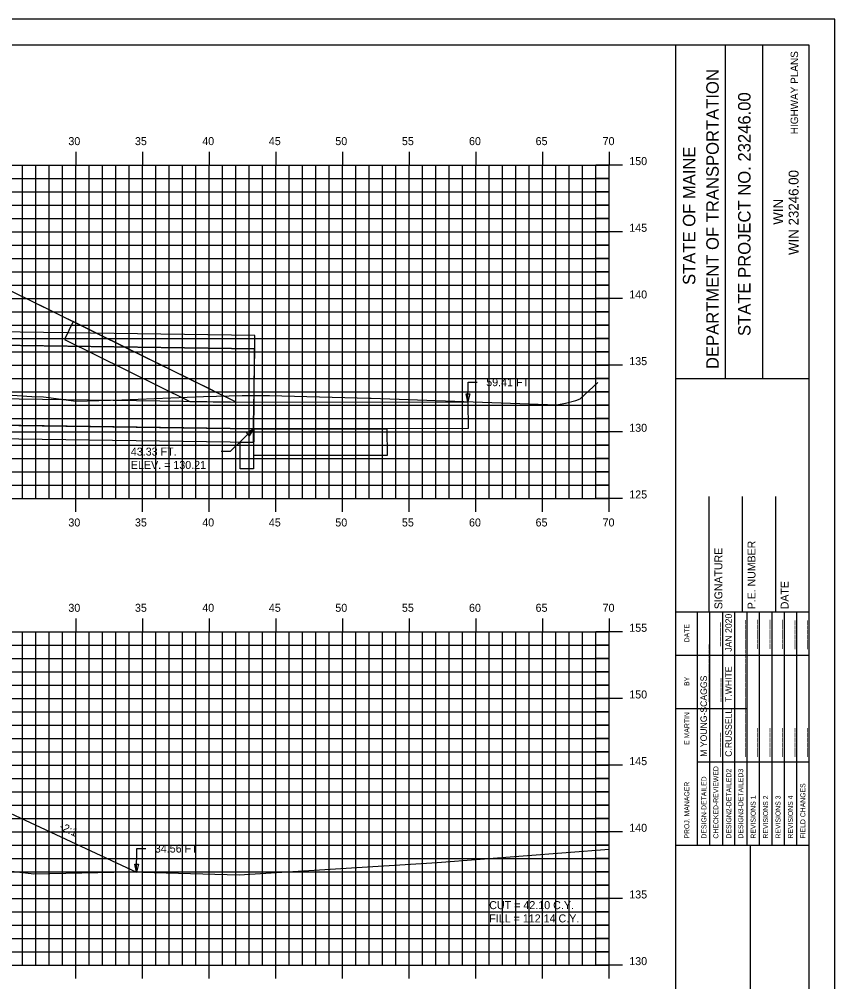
# Model space of a CAD drawing. Extents: x 1143863 to 1144033, y 608981 to 609091.
# Drawn here: x 1143972.4 to 1144033.5, y 609019.1 to 609091.3 of the extents above; entities that cross this region are included whole.
import ezdxf

# ---------------------------------------------------------------- set-up
doc = ezdxf.new("R2010")
doc.units = 0
for name, color, linetype in [('ANNOTATION', 7, 'Continuous'), ('BORDER', 7, 'Continuous'), ('D_Drainage_Culvert', 7, 'Continuous'), ('D_Roadway_SlopeLines', 7, 'Continuous'), ('D_Text_Standard', 7, 'Continuous'), ('H_V ANNOTATION', 7, 'Continuous'), ('HIGHWAY_TITLE', 7, 'Continuous'), ('MAJOR', 7, 'Continuous'), ('MINOR', 7, 'Continuous'), ('PATTERNING', 7, 'Continuous'), ('PLOT BOUNDARY', 7, 'Continuous'), ('S_Roadway_Centerline', 7, 'Continuous')]:
    doc.layers.add(name, color=color, linetype=linetype)

msp = doc.modelspace()

# ---------------------------------------------------------------- linework, layer by layer
for points in [[(1143971.726, 609070.91), (1143973.407, 609070.08), (1143974.229, 609069.674), (1143978.455, 609067.588), (1143981.694, 609065.99), (1143983.555, 609065.071), (1143987.715, 609063.019)], [(1143915.832, 609031.661), (1143916.276, 609031.761), (1143916.721, 609031.769), (1143917.165, 609031.685), (1143917.609, 609031.509), (1143921.469, 609032.509), (1143931.592, 609035.131), (1143931.593, 609035.131), (1143935.593, 609035.291), (1143946.593, 609035.511), (1143957.593, 609035.291), (1143964.593, 609035.011), (1143969.901, 609032.545), (1143972.053, 609031.545), (1143981.155, 609027.316)]]:
    msp.add_lwpolyline(points)
at = {"layer": 'BORDER'}
for p, q in [((1144021.593, 608984.335), (1144021.593, 609089.335)), ((1144025.321, 609064.332), (1144025.321, 609089.332)), ((1144028.117, 609064.332), (1144028.117, 609089.332)), ((1144021.594, 609064.329), (1144031.593, 609064.329)), ((1144024.093, 609046.838), (1144024.093, 609055.485)), ((1144026.593, 609046.838), (1144026.593, 609055.485)), ((1144029.093, 609046.838), (1144029.093, 609055.485)), ((1144021.593, 609046.838), (1144031.593, 609046.838)), ((1144021.593, 609029.338), (1144031.593, 609029.338)), ((1144027.184, 608994.338), (1144027.184, 609029.338))]:
    msp.add_line(p, q, dxfattribs=at)
msp.add_lwpolyline([(1143871.593, 608984.335), (1144031.593, 608984.335), (1144031.593, 609089.335), (1143871.593, 609089.335)], close=True, dxfattribs=at)
for points in [[(1144023.208, 609043.588), (1144023.208, 609046.838)], [(1144024.14, 609029.341), (1144024.14, 609046.838)], [(1144025.072, 609046.838), (1144025.072, 609029.341)], [(1144026.004, 609029.341), (1144026.004, 609046.838)], [(1144026.935, 609029.341), (1144026.935, 609046.838)], [(1144027.867, 609029.341), (1144027.867, 609046.838)], [(1144028.799, 609029.341), (1144028.799, 609046.838)], [(1144029.73, 609029.341), (1144029.73, 609046.838)], [(1144030.662, 609029.341), (1144030.662, 609046.838)], [(1144023.209, 609029.341), (1144023.209, 609046.132)], [(1144021.593, 609043.588), (1144031.593, 609043.588)], [(1144021.593, 609039.588), (1144023.209, 609039.588)], [(1144023.208, 609039.588), (1144026.934, 609039.588)], [(1144023.208, 609035.588), (1144031.593, 609035.588)]]:
    msp.add_lwpolyline(points, dxfattribs=at)
at = {"layer": 'D_Drainage_Culvert'}
for points in [[(1143901.91, 609060.818), (1143989.91, 609059.548), (1143990.025, 609067.547), (1143902.025, 609068.817)], [(1143901.924, 609061.817), (1143989.924, 609060.547), (1143990.011, 609066.547), (1143902.011, 609067.817)], [(1143989.91, 609059.548), (1143989.91, 609057.548), (1143988.91, 609057.548), (1143988.91, 609059.548)]]:
    msp.add_lwpolyline(points, close=True, dxfattribs=at)
at = {"layer": 'D_Roadway_SlopeLines'}
for points in [[(1143971.726, 609070.911), (1143986.896, 609063.424)], [(1143972.053, 609031.545), (1143981.155, 609027.316)]]:
    msp.add_lwpolyline(points, dxfattribs=at)
at = {"layer": 'D_Text_Standard'}
for points in [[(1144006.003, 609062.592), (1144006.009, 609064.057), (1144006.689, 609064.057)], [(1143989.924, 609060.547), (1143988.177, 609058.849), (1143987.497, 609058.849)], [(1143981.155, 609027.316), (1143981.165, 609029.079), (1143981.845, 609029.079)]]:
    msp.add_lwpolyline(points, dxfattribs=at)
for points in [[(1144006.003, 609062.592), (1144005.86, 609063.175), (1144006.151, 609063.173)], [(1143989.924, 609060.547), (1143989.608, 609060.037), (1143989.405, 609060.246)], [(1143981.155, 609027.316), (1143981.013, 609027.899), (1143981.304, 609027.897)]]:
    msp.add_lwpolyline(points, close=True, dxfattribs=at)
at = {"layer": 'MAJOR'}
for p, q in [((1143976.593, 609081.337), (1143976.593, 609080.335)), ((1143981.593, 609081.337), (1143981.593, 609080.335)), ((1143986.593, 609081.337), (1143986.593, 609080.335)), ((1143991.593, 609081.337), (1143991.593, 609080.335)), ((1143996.593, 609081.337), (1143996.593, 609080.335)), ((1144001.593, 609081.337), (1144001.593, 609080.335)), ((1144006.593, 609081.337), (1144006.593, 609080.335)), ((1144011.593, 609081.337), (1144011.593, 609080.335)), ((1144016.593, 609081.337), (1144016.593, 609080.335)), ((1143876.593, 609080.335), (1144016.593, 609080.335)), ((1143876.593, 609080.335), (1144016.593, 609080.335)), ((1143976.593, 609055.335), (1143976.593, 609080.335)), ((1143981.593, 609055.335), (1143981.593, 609080.335)), ((1143986.593, 609055.335), (1143986.593, 609080.335)), ((1143991.593, 609055.335), (1143991.593, 609080.335)), ((1143996.593, 609055.335), (1143996.593, 609080.335)), ((1144001.593, 609055.335), (1144001.593, 609080.335)), ((1144006.593, 609055.335), (1144006.593, 609080.335)), ((1144011.593, 609055.335), (1144011.593, 609080.335)), ((1144017.595, 609080.335), (1144015.591, 609080.335)), ((1144016.593, 609055.335), (1144016.593, 609080.335)), ((1144016.593, 609055.335), (1144016.593, 609080.335)), ((1143876.593, 609075.335), (1144016.593, 609075.335)), ((1144017.595, 609075.335), (1144015.591, 609075.335)), ((1143876.593, 609070.335), (1144016.593, 609070.335)), ((1144017.595, 609070.335), (1144015.591, 609070.335)), ((1143876.593, 609065.335), (1144016.593, 609065.335)), ((1144017.595, 609065.335), (1144015.591, 609065.335)), ((1143876.593, 609060.335), (1144016.593, 609060.335)), ((1144017.595, 609060.335), (1144015.591, 609060.335)), ((1143876.593, 609055.335), (1144016.593, 609055.335)), ((1143876.593, 609055.335), (1144016.593, 609055.335)), ((1143976.593, 609054.333), (1143976.593, 609055.335)), ((1143981.593, 609054.333), (1143981.593, 609055.335)), ((1143986.593, 609054.333), (1143986.593, 609055.335)), ((1143991.593, 609054.333), (1143991.593, 609055.335)), ((1143996.593, 609054.333), (1143996.593, 609055.335)), ((1144001.593, 609054.333), (1144001.593, 609055.335)), ((1144006.593, 609054.333), (1144006.593, 609055.335)), ((1144011.593, 609054.333), (1144011.593, 609055.335)), ((1144017.595, 609055.335), (1144015.591, 609055.335)), ((1144016.593, 609054.333), (1144016.593, 609055.335)), ((1143976.593, 609046.337), (1143976.593, 609045.335)), ((1143981.593, 609046.337), (1143981.593, 609045.335)), ((1143986.593, 609046.337), (1143986.593, 609045.335)), ((1143991.593, 609046.337), (1143991.593, 609045.335)), ((1143996.593, 609046.337), (1143996.593, 609045.335)), ((1144001.593, 609046.337), (1144001.593, 609045.335)), ((1144006.593, 609046.337), (1144006.593, 609045.335)), ((1144011.593, 609046.337), (1144011.593, 609045.335)), ((1144016.593, 609046.337), (1144016.593, 609045.335)), ((1143876.593, 609045.335), (1144016.593, 609045.335)), ((1143876.593, 609045.335), (1144016.593, 609045.335)), ((1143976.593, 609020.335), (1143976.593, 609045.335)), ((1143981.593, 609020.335), (1143981.593, 609045.335)), ((1143986.593, 609020.335), (1143986.593, 609045.335)), ((1143991.593, 609020.335), (1143991.593, 609045.335)), ((1143996.593, 609020.335), (1143996.593, 609045.335)), ((1144001.593, 609020.335), (1144001.593, 609045.335)), ((1144006.593, 609020.335), (1144006.593, 609045.335)), ((1144011.593, 609020.335), (1144011.593, 609045.335)), ((1144017.595, 609045.335), (1144015.591, 609045.335)), ((1144016.593, 609020.335), (1144016.593, 609045.335)), ((1144016.593, 609020.335), (1144016.593, 609045.335)), ((1143876.593, 609040.335), (1144016.593, 609040.335)), ((1144017.595, 609040.335), (1144015.591, 609040.335)), ((1143876.593, 609035.335), (1144016.593, 609035.335)), ((1144017.595, 609035.335), (1144015.591, 609035.335)), ((1143876.593, 609030.335), (1144016.593, 609030.335)), ((1144017.595, 609030.335), (1144015.591, 609030.335)), ((1143876.593, 609025.335), (1144016.593, 609025.335)), ((1144017.595, 609025.335), (1144015.591, 609025.335)), ((1143876.593, 609020.335), (1144016.593, 609020.335)), ((1143876.593, 609020.335), (1144016.593, 609020.335)), ((1143976.593, 609019.333), (1143976.593, 609020.335)), ((1143981.593, 609019.333), (1143981.593, 609020.335)), ((1143986.593, 609019.333), (1143986.593, 609020.335)), ((1143991.593, 609019.333), (1143991.593, 609020.335)), ((1143996.593, 609019.333), (1143996.593, 609020.335)), ((1144001.593, 609019.333), (1144001.593, 609020.335)), ((1144006.593, 609019.333), (1144006.593, 609020.335)), ((1144011.593, 609019.333), (1144011.593, 609020.335)), ((1144017.595, 609020.335), (1144015.591, 609020.335)), ((1144016.593, 609019.333), (1144016.593, 609020.335))]:
    msp.add_line(p, q, dxfattribs=at)
at = {"layer": 'MINOR'}
for p, q in [((1143972.593, 609055.335), (1143972.593, 609080.335)), ((1143973.593, 609055.335), (1143973.593, 609080.335)), ((1143974.593, 609055.335), (1143974.593, 609080.335)), ((1143975.593, 609055.335), (1143975.593, 609080.335)), ((1143977.593, 609055.335), (1143977.593, 609080.335)), ((1143978.593, 609055.335), (1143978.593, 609080.335)), ((1143979.593, 609055.335), (1143979.593, 609080.335)), ((1143980.593, 609055.335), (1143980.593, 609080.335)), ((1143982.593, 609055.335), (1143982.593, 609080.335)), ((1143983.593, 609055.335), (1143983.593, 609080.335)), ((1143984.593, 609055.335), (1143984.593, 609080.335)), ((1143985.593, 609055.335), (1143985.593, 609080.335)), ((1143987.593, 609055.335), (1143987.593, 609080.335)), ((1143988.593, 609055.335), (1143988.593, 609080.335)), ((1143989.593, 609055.335), (1143989.593, 609080.335)), ((1143990.593, 609055.335), (1143990.593, 609080.335)), ((1143992.593, 609055.335), (1143992.593, 609080.335)), ((1143993.593, 609055.335), (1143993.593, 609080.335)), ((1143994.593, 609055.335), (1143994.593, 609080.335)), ((1143995.593, 609055.335), (1143995.593, 609080.335)), ((1143997.593, 609055.335), (1143997.593, 609080.335)), ((1143998.593, 609055.335), (1143998.593, 609080.335)), ((1143999.593, 609055.335), (1143999.593, 609080.335)), ((1144000.593, 609055.335), (1144000.593, 609080.335)), ((1144002.593, 609055.335), (1144002.593, 609080.335)), ((1144003.593, 609055.335), (1144003.593, 609080.335)), ((1144004.593, 609055.335), (1144004.593, 609080.335)), ((1144005.593, 609055.335), (1144005.593, 609080.335)), ((1144007.593, 609055.335), (1144007.593, 609080.335)), ((1144008.593, 609055.335), (1144008.593, 609080.335)), ((1144009.593, 609055.335), (1144009.593, 609080.335)), ((1144010.593, 609055.335), (1144010.593, 609080.335)), ((1144012.593, 609055.335), (1144012.593, 609080.335)), ((1144013.593, 609055.335), (1144013.593, 609080.335)), ((1144014.593, 609055.335), (1144014.593, 609080.335)), ((1144015.593, 609055.335), (1144015.593, 609080.335)), ((1143876.593, 609079.335), (1144016.593, 609079.335)), ((1144016.593, 609079.335), (1144015.591, 609079.335)), ((1143876.593, 609078.335), (1144016.593, 609078.335)), ((1144016.593, 609078.335), (1144015.591, 609078.335)), ((1143876.593, 609077.335), (1144016.593, 609077.335)), ((1144016.593, 609077.335), (1144015.591, 609077.335)), ((1143876.593, 609076.335), (1144016.593, 609076.335)), ((1144016.593, 609076.335), (1144015.591, 609076.335)), ((1143876.593, 609074.335), (1144016.593, 609074.335)), ((1144016.593, 609074.335), (1144015.591, 609074.335)), ((1143876.593, 609073.335), (1144016.593, 609073.335)), ((1144016.593, 609073.335), (1144015.591, 609073.335)), ((1143876.593, 609072.335), (1144016.593, 609072.335)), ((1144016.593, 609072.335), (1144015.591, 609072.335)), ((1143876.593, 609071.335), (1144016.593, 609071.335)), ((1144016.593, 609071.335), (1144015.591, 609071.335)), ((1143876.593, 609069.335), (1144016.593, 609069.335)), ((1144016.593, 609069.335), (1144015.591, 609069.335)), ((1143876.593, 609068.335), (1144016.593, 609068.335)), ((1144016.593, 609068.335), (1144015.591, 609068.335)), ((1143876.593, 609067.335), (1144016.593, 609067.335)), ((1144016.593, 609067.335), (1144015.591, 609067.335)), ((1143876.593, 609066.335), (1144016.593, 609066.335)), ((1144016.593, 609066.335), (1144015.591, 609066.335)), ((1143876.593, 609064.335), (1144016.593, 609064.335)), ((1144016.593, 609064.335), (1144015.591, 609064.335)), ((1143876.593, 609063.335), (1144016.593, 609063.335)), ((1144016.593, 609063.335), (1144015.591, 609063.335)), ((1143876.593, 609062.335), (1144016.593, 609062.335)), ((1144016.593, 609062.335), (1144015.591, 609062.335)), ((1143876.593, 609061.335), (1144016.593, 609061.335)), ((1144016.593, 609061.335), (1144015.591, 609061.335)), ((1143876.593, 609059.335), (1144016.593, 609059.335)), ((1144016.593, 609059.335), (1144015.591, 609059.335)), ((1143876.593, 609058.335), (1144016.593, 609058.335)), ((1144016.593, 609058.335), (1144015.591, 609058.335)), ((1143876.593, 609057.335), (1144016.593, 609057.335)), ((1144016.593, 609057.335), (1144015.591, 609057.335)), ((1143876.593, 609056.335), (1144016.593, 609056.335)), ((1144016.593, 609056.335), (1144015.591, 609056.335)), ((1143972.593, 609020.335), (1143972.593, 609045.335)), ((1143973.593, 609020.335), (1143973.593, 609045.335)), ((1143974.593, 609020.335), (1143974.593, 609045.335)), ((1143975.593, 609020.335), (1143975.593, 609045.335)), ((1143977.593, 609020.335), (1143977.593, 609045.335)), ((1143978.593, 609020.335), (1143978.593, 609045.335)), ((1143979.593, 609020.335), (1143979.593, 609045.335)), ((1143980.593, 609020.335), (1143980.593, 609045.335)), ((1143982.593, 609020.335), (1143982.593, 609045.335)), ((1143983.593, 609020.335), (1143983.593, 609045.335)), ((1143984.593, 609020.335), (1143984.593, 609045.335)), ((1143985.593, 609020.335), (1143985.593, 609045.335)), ((1143987.593, 609020.335), (1143987.593, 609045.335)), ((1143988.593, 609020.335), (1143988.593, 609045.335)), ((1143989.593, 609020.335), (1143989.593, 609045.335)), ((1143990.593, 609020.335), (1143990.593, 609045.335)), ((1143992.593, 609020.335), (1143992.593, 609045.335)), ((1143993.593, 609020.335), (1143993.593, 609045.335)), ((1143994.593, 609020.335), (1143994.593, 609045.335)), ((1143995.593, 609020.335), (1143995.593, 609045.335)), ((1143997.593, 609020.335), (1143997.593, 609045.335)), ((1143998.593, 609020.335), (1143998.593, 609045.335)), ((1143999.593, 609020.335), (1143999.593, 609045.335)), ((1144000.593, 609020.335), (1144000.593, 609045.335)), ((1144002.593, 609020.335), (1144002.593, 609045.335)), ((1144003.593, 609020.335), (1144003.593, 609045.335)), ((1144004.593, 609020.335), (1144004.593, 609045.335)), ((1144005.593, 609020.335), (1144005.593, 609045.335)), ((1144007.593, 609020.335), (1144007.593, 609045.335)), ((1144008.593, 609020.335), (1144008.593, 609045.335)), ((1144009.593, 609020.335), (1144009.593, 609045.335)), ((1144010.593, 609020.335), (1144010.593, 609045.335)), ((1144012.593, 609020.335), (1144012.593, 609045.335)), ((1144013.593, 609020.335), (1144013.593, 609045.335)), ((1144014.593, 609020.335), (1144014.593, 609045.335)), ((1144015.593, 609020.335), (1144015.593, 609045.335)), ((1143876.593, 609044.335), (1144016.593, 609044.335)), ((1144016.593, 609044.335), (1144015.591, 609044.335)), ((1143876.593, 609043.335), (1144016.593, 609043.335)), ((1144016.593, 609043.335), (1144015.591, 609043.335)), ((1143876.593, 609042.335), (1144016.593, 609042.335)), ((1144016.593, 609042.335), (1144015.591, 609042.335)), ((1143876.593, 609041.335), (1144016.593, 609041.335)), ((1144016.593, 609041.335), (1144015.591, 609041.335)), ((1143876.593, 609039.335), (1144016.593, 609039.335)), ((1144016.593, 609039.335), (1144015.591, 609039.335)), ((1143876.593, 609038.335), (1144016.593, 609038.335)), ((1144016.593, 609038.335), (1144015.591, 609038.335)), ((1143876.593, 609037.335), (1144016.593, 609037.335)), ((1144016.593, 609037.335), (1144015.591, 609037.335)), ((1143876.593, 609036.335), (1144016.593, 609036.335)), ((1144016.593, 609036.335), (1144015.591, 609036.335)), ((1143876.593, 609034.335), (1144016.593, 609034.335)), ((1144016.593, 609034.335), (1144015.591, 609034.335)), ((1143876.593, 609033.335), (1144016.593, 609033.335)), ((1144016.593, 609033.335), (1144015.591, 609033.335)), ((1143876.593, 609032.335), (1144016.593, 609032.335)), ((1144016.593, 609032.335), (1144015.591, 609032.335)), ((1143876.593, 609031.335), (1144016.593, 609031.335)), ((1144016.593, 609031.335), (1144015.591, 609031.335)), ((1143876.593, 609029.335), (1144016.593, 609029.335)), ((1144016.593, 609029.335), (1144015.591, 609029.335)), ((1143876.593, 609028.335), (1144016.593, 609028.335)), ((1144016.593, 609028.335), (1144015.591, 609028.335)), ((1143876.593, 609027.335), (1144016.593, 609027.335)), ((1144016.593, 609027.335), (1144015.591, 609027.335)), ((1143876.593, 609026.335), (1144016.593, 609026.335)), ((1144016.593, 609026.335), (1144015.591, 609026.335)), ((1143876.593, 609024.335), (1144016.593, 609024.335)), ((1144016.593, 609024.335), (1144015.591, 609024.335)), ((1143876.593, 609023.335), (1144016.593, 609023.335)), ((1144016.593, 609023.335), (1144015.591, 609023.335)), ((1143876.593, 609022.335), (1144016.593, 609022.335)), ((1144016.593, 609022.335), (1144015.591, 609022.335)), ((1143876.593, 609021.335), (1144016.593, 609021.335)), ((1144016.593, 609021.335), (1144015.591, 609021.335))]:
    msp.add_line(p, q, dxfattribs=at)
at = {"layer": 'PATTERNING'}
for p, q in [((1143902.011, 609067.817), (1143990.011, 609066.547)), ((1143990.011, 609066.547), (1143990.025, 609067.547)), ((1143989.924, 609060.547), (1143901.924, 609061.817))]:
    msp.add_line(p, q, dxfattribs=at)
for points in [[(1143990.025, 609067.547), (1143902.025, 609068.817), (1143902.011, 609067.817)], [(1143901.91, 609060.818), (1143989.91, 609059.548), (1143989.924, 609060.547)]]:
    msp.add_lwpolyline(points, dxfattribs=at)
for points in [[(1143988.633, 609062.566), (1143978.196, 609067.717), (1143976.403, 609068.603), (1143975.739, 609067.257), (1143985.142, 609062.617)], [(1143989.924, 609060.547), (1143901.924, 609061.817), (1143901.953, 609063.817), (1143989.953, 609062.547)], [(1143989.953, 609062.547), (1144006.003, 609062.592), (1144006.014, 609060.592), (1143989.924, 609060.547)], [(1143989.964, 609060.547), (1143999.924, 609060.566), (1143999.935, 609058.566), (1143989.935, 609058.547)]]:
    msp.add_lwpolyline(points, close=True, dxfattribs=at)
at = {"layer": 'PLOT BOUNDARY'}
msp.add_lwpolyline([(1143863.5, 608981.276), (1144033.5, 608981.276), (1144033.5, 609091.276), (1143863.5, 609091.276)], close=True, dxfattribs=at)
at = {"layer": 'S_Roadway_Centerline'}
for points in [[(1143968.124, 609063.336), (1143973.298, 609062.981), (1143974.183, 609062.947), (1143976.618, 609062.639), (1143980.052, 609062.741), (1143986.164, 609062.97), (1143989.07, 609063.066), (1143991.113, 609063.058), (1143992.041, 609063.022), (1143998.631, 609062.867), (1143998.683, 609062.864), (1143998.755, 609062.853), (1144012.663, 609062.352), (1144013.325, 609062.47), (1144014.08, 609062.691), (1144014.423, 609062.803), (1144015.729, 609064.028)], [(1143876.593, 609028.445), (1143880.764, 609028.537), (1143893.48, 609029.427), (1143907.327, 609030.275), (1143911.989, 609030.655), (1143912.996, 609030.602), (1143915.271, 609031.477), (1143918.046, 609032.388), (1143921.473, 609032.795), (1143921.72, 609032.822), (1143931.839, 609033.205), (1143932.613, 609033.238), (1143933.341, 609033.203), (1143943.019, 609032.935), (1143943.336, 609032.897), (1143946.452, 609032.294), (1143947.313, 609031.983), (1143956.366, 609028.867), (1143960.542, 609028.707), (1143973.447, 609027.173), (1143980.648, 609027.329), (1143988.842, 609027.119), (1144003.679, 609028.03), (1144016.593, 609029.026)]]:
    msp.add_lwpolyline(points, dxfattribs=at)

# ---------------------------------------------------------------- texts
at = {"layer": 'ANNOTATION'}
msp.add_text('-2:1', height=0.6, rotation=335.0805, dxfattribs=at).set_placement((1143975.317, 609030.531))
at = {"layer": 'BORDER'}
for s, height, p in [('DEPARTMENT OF TRANSPORTATION', 0.93176, (1144024.8, 609065.041)), ('STATE PROJECT NO. 23246.00', 0.93176, (1144027.185, 609067.517)), ('STATE OF MAINE', 0.93176, (1144023.048, 609071.347)), ('WIN 23246.00', 0.74527, (1144030.788, 609073.596)), ('WIN', 0.7453, (1144029.63, 609075.865)), ('SIGNATURE', 0.5906, (1144025.073, 609047.03)), ('P.E. NUMBER', 0.59055, (1144027.554, 609047.03)), ('DATE', 0.5906, (1144030.034, 609047.03)), ('JAN 2020', 0.4845, (1144025.779, 609043.843)), ('DATE', 0.3714, (1144022.597, 609044.544)), ('_____', 0.4845, (1144024.81, 609044.243)), ('______', 0.4845, (1144026.674, 609044.063)), ('______', 0.4845, (1144027.605, 609044.065)), ('______', 0.4845, (1144028.537, 609044.067)), ('______', 0.4845, (1144029.469, 609044.067)), ('______', 0.4845, (1144030.4, 609044.036)), ('______', 0.4845, (1144031.332, 609044.036)), ('____________', 0.48455, (1144023.916, 609040.073)), ('____________', 0.48455, (1144026.674, 609040.073)), ('T.WHITE', 0.4845, (1144025.779, 609040.073)), ('BY', 0.3714, (1144022.597, 609041.273)), ('M YOUNG-SCAGGS', 0.48455, (1144023.916, 609035.961)), ('_____', 0.4845, (1144024.848, 609040.073)), ('____________', 0.48455, (1144026.674, 609035.961)), ('C.RUSSELL', 0.4845, (1144025.779, 609035.961)), ('E MARTIN', 0.3727, (1144022.597, 609036.855)), ('_____', 0.4845, (1144024.81, 609035.961)), ('______', 0.4845, (1144027.605, 609035.961)), ('______', 0.4845, (1144028.537, 609035.961)), ('______', 0.4845, (1144029.469, 609035.961)), ('______', 0.4845, (1144030.4, 609035.961)), ('______', 0.4845, (1144031.332, 609035.961)), ('CHECKED-REVIEWED', 0.37275, (1144024.774, 609029.826)), ('DESIGN2-DETAILED2', 0.37275, (1144025.743, 609029.826)), ('DESIGN3-DETAILED3', 0.37275, (1144026.637, 609029.826)), ('DESIGN-DETAILED', 0.37275, (1144023.879, 609029.826)), ('PROJ. MANAGER', 0.37275, (1144022.597, 609029.826)), ('FIELD CHANGES', 0.37275, (1144031.296, 609029.826)), ('REVISIONS 1', 0.37275, (1144027.569, 609029.826)), ('REVISIONS 2', 0.37275, (1144028.501, 609029.826)), ('REVISIONS 3', 0.37275, (1144029.432, 609029.826)), ('REVISIONS 4', 0.37275, (1144030.364, 609029.826))]:
    msp.add_text(s, height=height, rotation=90, dxfattribs=at).set_placement(p)
at = {"layer": 'D_Text_Standard'}
for s, p in [('59.41 FT', (1144007.369, 609063.757)), ('43.33 FT.', (1143980.723, 609058.549)), ('ELEV. = 130.21', (1143980.723, 609057.549)), ('34.56 FT', (1143982.525, 609028.779)), ('CUT = 42.10 C.Y.', (1144007.593, 609024.535)), ('FILL = 112.14 C.Y.', (1144007.593, 609023.539))]:
    msp.add_text(s, height=0.6, dxfattribs=at).set_placement(p)
at = {"layer": 'H_V ANNOTATION'}
for s, p in [('30', (1143976.041, 609081.835)), ('35', (1143981.033, 609081.835)), ('40', (1143986.079, 609081.835)), ('45', (1143991.071, 609081.835)), ('50', (1143996.057, 609081.835)), ('55', (1144001.049, 609081.835)), ('60', (1144006.079, 609081.835)), ('65', (1144011.071, 609081.835)), ('70', (1144016.095, 609081.835)), ('150', (1144018.093, 609080.335)), ('145', (1144018.093, 609075.335)), ('140', (1144018.093, 609070.335)), ('135', (1144018.093, 609065.335)), ('130', (1144018.093, 609060.335)), ('125', (1144018.093, 609055.335)), ('30', (1143976.041, 609053.235)), ('35', (1143981.033, 609053.235)), ('40', (1143986.079, 609053.235)), ('45', (1143991.071, 609053.235)), ('50', (1143996.057, 609053.235)), ('55', (1144001.049, 609053.235)), ('60', (1144006.079, 609053.235)), ('65', (1144011.071, 609053.235)), ('70', (1144016.095, 609053.235)), ('30', (1143976.041, 609046.835)), ('35', (1143981.033, 609046.835)), ('40', (1143986.079, 609046.835)), ('45', (1143991.071, 609046.835)), ('50', (1143996.057, 609046.835)), ('55', (1144001.049, 609046.835)), ('60', (1144006.079, 609046.835)), ('65', (1144011.071, 609046.835)), ('70', (1144016.095, 609046.835)), ('155', (1144018.093, 609045.335)), ('150', (1144018.093, 609040.335)), ('145', (1144018.093, 609035.335)), ('140', (1144018.093, 609030.335)), ('135', (1144018.093, 609025.335)), ('130', (1144018.093, 609020.335))]:
    msp.add_text(s, height=0.6, dxfattribs=at).set_placement(p)
at = {"layer": 'HIGHWAY_TITLE'}
msp.add_text('HIGHWAY PLANS', height=0.55901, rotation=90, dxfattribs=at).set_placement((1144030.751, 609082.65))

doc.saveas('drawing.dxf')
